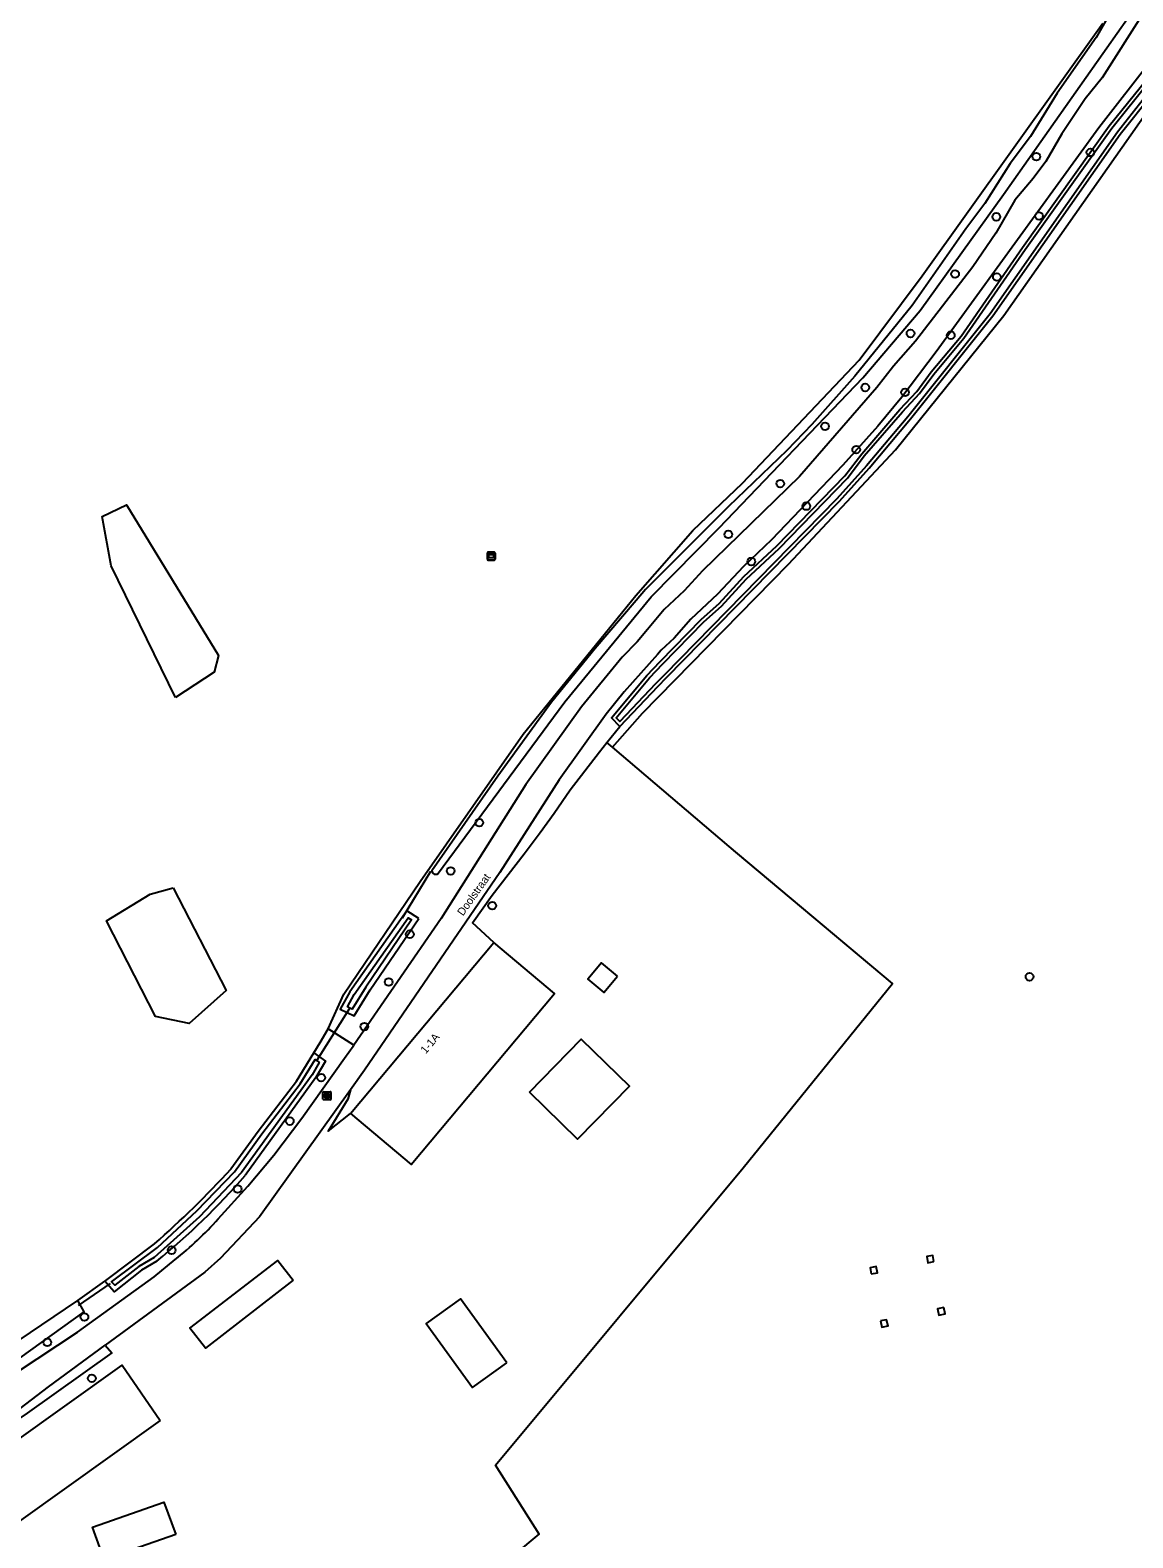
# Model space of a CAD drawing. Extents: x 164494 to 166241, y 382475 to 384494.
# Drawn here: x 165159.3 to 165298.8, y 383046.7 to 383237.3 of the extents above; entities that cross this region are included whole.
import ezdxf

# ---------------------------------------------------------------- set-up
doc = ezdxf.new("R2010")
doc.units = 0
for name, color, linetype in [('IMGEO_Boom', 7, 'Continuous'), ('IMGEO_Bouwland', 7, 'Continuous'), ('IMGEO_Duiker', 7, 'Continuous'), ('IMGEO_Grasland_overig', 7, 'Continuous'), ('IMGEO_Groenvoorziening', 7, 'Continuous'), ('IMGEO_Hek', 7, 'Continuous'), ('IMGEO_Hoogspanningsmast', 7, 'Continuous'), ('IMGEO_Loofbos', 7, 'Continuous'), ('IMGEO_Openbare_ruimte_label', 7, 'Continuous'), ('IMGEO_Pand', 7, 'Continuous'), ('IMGEO_Pand_nummerreeks', 7, 'Continuous'), ('IMGEO_Rijbaan_lokaal_halfverhard', 7, 'Continuous'), ('IMGEO_Rioolput', 7, 'Continuous'), ('IMGEO_Verklikker', 7, 'Continuous'), ('IMGEO_Waterloop', 7, 'Continuous')]:
    doc.layers.add(name, color=color, linetype=linetype)

msp = doc.modelspace()

# ---------------------------------------------------------------- linework, layer by layer
at = {"layer": 'IMGEO_Boom'}
for centre in [(165286.55, 383221.31), (165293.39, 383221.84), (165281.49, 383213.7), (165286.9, 383213.81), (165276.28, 383206.47), (165281.56, 383206.08), (165270.64, 383198.95), (165275.73, 383198.73), (165264.91, 383192.12), (165269.95, 383191.5), (165259.83, 383187.21), (165263.77, 383184.27), (165254.16, 383179.97), (165257.46, 383177.12), (165247.59, 383173.54), (165250.5, 383170.11), (165216.09, 383137.1), (165212.48, 383130.99), (165217.73, 383126.59), (165207.31, 383122.99), (165285.69, 383117.6), (165204.64, 383116.94), (165201.56, 383111.31), (165196.1, 383104.86), (165192.13, 383099.35), (165185.53, 383090.77), (165177.19, 383083.04), (165166.16, 383074.59), (165161.46, 383071.37), (165167.09, 383066.84)]:
    msp.add_circle(centre, 0.489, dxfattribs=at)
at = {"layer": 'IMGEO_Bouwland'}
for points in [[(165232.93, 383146.62), (165236.73, 383150.93), (165255.21, 383169.77), (165268.73, 383184.22), (165282.44, 383201.21), (165301.48, 383228.34), (165303.71, 383229.45), (165304.49, 383229.08), (165313.7, 383213.1), (165323.27, 383195.77), (165328.23, 383185.67), (165331.48, 383177.72), (165334.48, 383168.92), (165336.93, 383159.97), (165340.39, 383146.11), (165341.99, 383138.03)], [(165185, 383018.32), (165194.85, 383024.31), (165208.27, 383034.25), (165223.66, 383047.14), (165218.15, 383055.85), (165249.48, 383093.43), (165268.36, 383116.74), (165247.72, 383134.08), (165232.93, 383146.62)], [(165184.69, 383093.31), (165188.14, 383098.1), (165192.97, 383104.4), (165195.15, 383107.98)], [(165168.73, 383079.13), (165168.86, 383079.22), (165175, 383083.84)]]:
    msp.add_lwpolyline(points, dxfattribs=at)
msp.add_arc((165091.58, 383178.94), 126.51, 311.2584, 317.3955, dxfattribs=at)
at = {"layer": 'IMGEO_Duiker'}
for points in [[(165209.93, 383130.92), (165206.34, 383125)], [(165195.55, 383107.03), (165199.72, 383113.65)], [(165165.42, 383076.05), (165169.45, 383078.84)]]:
    msp.add_lwpolyline(points, dxfattribs=at)
at = {"layer": 'IMGEO_Grasland_overig'}
for points in [[(165197, 383111.02), (165198.96, 383115.4), (165208.62, 383129.64), (165221.63, 383148.27), (165235.88, 383165.81), (165243.09, 383174.04), (165249.4, 383180.04), (165264.13, 383195.59), (165272.13, 383206.26), (165294.98, 383238.21)], [(165233.88, 383149.26), (165232.83, 383150.35), (165237.3, 383155.71), (165238.99, 383157.46), (165244.19, 383162.81), (165246.45, 383164.79), (165249.54, 383168.2), (165253.72, 383172.09), (165262.35, 383180.93), (165264.46, 383183.73), (165269.29, 383189.33), (165271.45, 383191.63), (165273.23, 383194.09), (165277.04, 383198.62), (165284.8, 383209.82), (165295.77, 383225.19), (165300.55, 383231.16), (165301.32, 383231.86)], [(165232.24, 383147.21), (165233.88, 383149.26)], [(165217.94, 383121.93), (165215.23, 383124.42), (165217.74, 383127.91), (165221.76, 383133.17), (165223.8, 383135.85), (165225.58, 383138.3), (165227.61, 383141.23), (165231.32, 383146.06), (165232.24, 383147.21)], [(165208.43, 383124.96), (165206.95, 383125.96), (165199.74, 383115.69), (165198.52, 383113.49), (165200.29, 383112.66), (165202.29, 383115.96), (165208.43, 383124.96)], [(165195.15, 383107.98), (165195.96, 383109.31), (165197, 383111.02)], [(165200.23, 383108.95), (165197, 383111.02)], [(165195.15, 383107.98), (165196.66, 383106.95), (165195.43, 383104.86), (165186.49, 383092.48)], [(165199.81, 383103.29), (165199.49, 383102.14), (165196.97, 383098.1), (165199.79, 383100.32)], [(165175.31, 383081.64), (165173.36, 383080.5), (165169.91, 383077.78), (165168.73, 383079.13)], [(165165.33, 383076.66), (165168.73, 383079.13)]]:
    msp.add_lwpolyline(points, dxfattribs=at)
msp.add_arc((165116.7, 383153.32), 92.59, 309.2748, 318.9253, dxfattribs=at)
at = {"layer": 'IMGEO_Groenvoorziening'}
for points in [[(165233.88, 383149.26), (165238.71, 383154.35), (165239.79, 383155.44), (165261.65, 383177.73), (165265.39, 383181.92), (165270.62, 383188.15), (165281.06, 383201.19), (165297.16, 383224.15), (165301.31, 383229.4)], [(165232.93, 383146.62), (165232.24, 383147.21)], [(165168.79, 383071.02), (165169.63, 383070.04), (165158.92, 383062.43), (165147.97, 383055.13)]]:
    msp.add_lwpolyline(points, dxfattribs=at)
at = {"layer": 'IMGEO_Hek'}
for points in [[(165232.93, 383146.62), (165232.24, 383147.21)], [(165248.56, 383133.37), (165247.72, 383134.08), (165232.93, 383146.62)], [(165249.48, 383093.43), (165268.36, 383116.74), (165248.56, 383133.37)]]:
    msp.add_lwpolyline(points, dxfattribs=at)
at = {"layer": 'IMGEO_Hoogspanningsmast'}
for points in [[(165273.6, 383081.59), (165273.45, 383082.38), (165272.68, 383082.22), (165272.83, 383081.42), (165273.6, 383081.59)], [(165265.68, 383080.04), (165266.46, 383080.19), (165266.31, 383080.98), (165265.52, 383080.82), (165265.68, 383080.04)], [(165274.84, 383075.77), (165274.06, 383075.6), (165274.22, 383074.82), (165275.01, 383074.98), (165274.84, 383075.77)], [(165266.83, 383074.08), (165266.99, 383073.31), (165267.79, 383073.47), (165267.62, 383074.24), (165266.83, 383074.08)]]:
    msp.add_lwpolyline(points, dxfattribs=at)
at = {"layer": 'IMGEO_Loofbos'}
for points in [[(165177.67, 383152.9), (165169.55, 383169.59), (165168.39, 383175.79), (165171.46, 383177.28), (165183.1, 383158.25), (165182.55, 383156.14), (165177.67, 383152.9)], [(165177.36, 383128.85), (165184.08, 383115.87), (165179.39, 383111.69), (165175.14, 383112.58), (165168.94, 383124.68), (165174.45, 383128.05), (165177.36, 383128.85)]]:
    msp.add_lwpolyline(points, dxfattribs=at)
at = {"layer": 'IMGEO_Pand'}
for points in [[(165199.79, 383100.32), (165217.94, 383121.93)], [(165199.79, 383100.32), (165207.5, 383093.85), (165225.63, 383115.48), (165217.94, 383121.93)], [(165233.58, 383117.67), (165231.57, 383119.36), (165229.84, 383117.3), (165231.86, 383115.61), (165233.58, 383117.67)], [(165222.44, 383103.02), (165229, 383109.72), (165235.09, 383103.76), (165228.53, 383097.06), (165222.44, 383103.02)], [(165192.55, 383079.23), (165181.45, 383070.63), (165179.49, 383073.16), (165190.61, 383081.75), (165192.55, 383079.23)], [(165219.57, 383068.78), (165213.7, 383076.89), (165209.36, 383073.75), (165215.23, 383065.65), (165219.57, 383068.78)], [(165175.75, 383061.48), (165157.81, 383048.67), (165156.81, 383050.14), (165153.69, 383047.91), (165150.01, 383053.56), (165170.91, 383068.49), (165175.75, 383061.48)], [(165177.7, 383047.09), (165168.67, 383043.94), (165167.16, 383048.01), (165176.19, 383051.16), (165177.7, 383047.09)]]:
    msp.add_lwpolyline(points, dxfattribs=at)
at = {"layer": 'IMGEO_Rijbaan_lokaal_halfverhard'}
for points in [[(165300.11, 383239.48), (165294.86, 383231.27), (165292.71, 383228.62), (165289.79, 383224.2), (165287.74, 383220.71), (165286.16, 383218.55), (165283.85, 383215.8), (165281.41, 383211.62), (165278.5, 383207.39), (165271.28, 383197.97), (165268.48, 383194.82), (165266.39, 383192.1), (165256.58, 383180.86), (165244.32, 383168.93), (165241.99, 383166.4), (165239.47, 383164.03), (165237.38, 383161.51), (165236.08, 383159.95), (165234.16, 383158.04), (165229.01, 383151.75), (165221.98, 383141.91), (165211.27, 383124.97), (165200.23, 383108.95)], [(165301.1, 383233.5), (165294.45, 383224.95), (165273.9, 383196.62), (165269.53, 383190.91), (165266.52, 383187.24), (165262.08, 383182.29), (165253.04, 383172.85), (165249.5, 383169.5), (165246.23, 383165.97), (165242.87, 383162.82), (165240.74, 383160.44), (165239.08, 383158.89), (165238.62, 383158.37), (165234.41, 383153.64), (165232.13, 383150.82), (165226.21, 383142.5), (165218.7, 383130.81), (165201.6, 383105.79), (165199.81, 383103.29)], [(165183.08, 383087), (165186.84, 383091.11), (165190.1, 383095.04), (165193.65, 383099.72), (165199.07, 383107.32), (165200.16, 383108.84), (165200.23, 383108.95)], [(165199.81, 383103.29), (165188.28, 383087.23), (165183.37, 383082.04), (165181.4, 383080.25), (165168.79, 383071.02)], [(165145.27, 383058.94), (165150.95, 383062.46), (165153.38, 383064.63), (165157.7, 383067.66), (165165.26, 383072.66), (165174.96, 383079.68), (165177.63, 383081.87)], [(165147.97, 383055.13), (165152.79, 383059.07), (165161.61, 383065.76), (165168.79, 383071.02)]]:
    msp.add_lwpolyline(points, dxfattribs=at)
msp.add_arc((165151.38, 383115.19), 42.42, 308.2249, 318.3405, dxfattribs=at)
at = {"layer": 'IMGEO_Rioolput'}
for p, q in [((165196.33, 383102.14), (165196.33, 383102.99)), ((165196.4, 383103.06), (165197.25, 383103.06)), ((165196.81, 383102.84), (165196.84, 383102.84)), ((165196.84, 383102.28), (165196.81, 383102.28)), ((165197.33, 383102.99), (165197.33, 383102.14)), ((165197.25, 383102.06), (165196.4, 383102.06))]:
    msp.add_line(p, q, dxfattribs=at)
for points in [[(165196.33, 383102.14), (165196.33, 383102.99)], [(165196.4, 383103.06), (165197.25, 383103.06)], [(165196.92, 383102.76), (165196.66, 383102.76), (165196.66, 383102.36)], [(165196.66, 383102.36), (165196.79, 383102.36), (165196.79, 383102.52), (165196.8, 383102.52)], [(165196.84, 383102.68), (165196.79, 383102.68), (165196.79, 383102.6)], [(165196.79, 383102.6), (165196.84, 383102.6)], [(165196.84, 383102.49), (165196.92, 383102.36), (165197.06, 383102.36), (165196.99, 383102.49)], [(165197.33, 383102.99), (165197.33, 383102.14)], [(165197.25, 383102.06), (165196.4, 383102.06)]]:
    msp.add_lwpolyline(points, dxfattribs=at)
for centre, radius, start, end in [((165196.4, 383102.99), 0.0765, 91.552, 178.448), ((165196.4, 383102.99), 0.0765, 91.552, 178.448), ((165196.8, 383102.47), 0.0533, 26.0293, 88.6989), ((165196.85, 383102.58), 0.0964, 77.0061, 93.1865), ((165196.82, 383102.79), 0.19, 274.7715, 282.9687), ((165196.86, 383102.64), 0.0378, 276.6634, 79.6772), ((165196.91, 383102.65), 0.109, 350.3612, 89.416), ((165196.91, 383102.65), 0.112, 277.5842, 350.9817), ((165196.9, 383102.43), 0.108, 29.5134, 73.7905), ((165197.25, 383102.99), 0.0765, 1.552, 88.448), ((165197.25, 383102.99), 0.0765, 1.552, 88.448), ((165196.4, 383102.14), 0.0765, 181.552, 268.448), ((165196.4, 383102.14), 0.0765, 181.552, 268.448), ((165197.25, 383102.14), 0.0765, 271.552, 358.448), ((165197.25, 383102.14), 0.0765, 271.552, 358.448)]:
    msp.add_arc(centre, radius, start, end, dxfattribs=at)
for centre, major_axis, ratio, start_param, end_param in [((165196.81, 383102.56), (-0.387, 0.002), 0.722429, 4.712389, 7.853982), ((165196.84, 383102.56), (-0.39, 0.002), 0.717154, 1.570796, 4.712389)]:
    msp.add_ellipse(centre, major_axis=major_axis, ratio=ratio, start_param=start_param, end_param=end_param, dxfattribs=at)
at = {"layer": 'IMGEO_Verklikker'}
for p, q in [((165217.12, 383170.4), (165217.12, 383171.19)), ((165217.12, 383171.19), (165217.12, 383170.4)), ((165217.22, 383171.29), (165218.01, 383171.29)), ((165218.01, 383171.29), (165217.22, 383171.29)), ((165218.11, 383171.19), (165218.11, 383170.4)), ((165218.11, 383170.4), (165218.11, 383171.19)), ((165218.01, 383170.3), (165217.22, 383170.3)), ((165217.22, 383170.3), (165218.01, 383170.3))]:
    msp.add_line(p, q, dxfattribs=at)
for points in [[(165217.22, 383171.03), (165218.01, 383171.03), (165218.01, 383170.56), (165217.22, 383170.56), (165217.22, 383171.03)], [(165217.28, 383170.96), (165217.28, 383170.63), (165217.94, 383170.63), (165217.94, 383170.96), (165217.28, 383170.96)]]:
    msp.add_lwpolyline(points, dxfattribs=at)
for centre, start, end in [((165217.22, 383171.19), 90, 180), ((165217.22, 383171.19), 90, 180), ((165218.01, 383171.19), 0, 90), ((165218.01, 383171.19), 360, 90), ((165217.22, 383170.4), 180, 270), ((165217.22, 383170.4), 180, 270), ((165218.01, 383170.4), 270, 0), ((165218.01, 383170.4), 270, 0)]:
    msp.add_arc(centre, 0.1, start, end, dxfattribs=at)
at = {"layer": 'IMGEO_Waterloop'}
for points in [[(165296.93, 383241.33), (165294.12, 383236.39), (165289.2, 383229.34), (165285.8, 383223.84), (165283.26, 383220.44), (165280.02, 383215.37), (165277.63, 383212.19), (165270.83, 383202.49), (165263.6, 383193.55), (165258.15, 383187.46), (165255.01, 383184.17), (165247.6, 383177.07), (165237.1, 383166.57), (165235.92, 383165.18), (165230.75, 383159.11), (165225.22, 383152.32), (165218.46, 383142.98), (165210.09, 383131.01), (165210.13, 383130.88), (165210.18, 383130.75), (165210.24, 383130.69), (165210.4, 383130.6), (165210.5, 383130.59), (165210.68, 383130.59), (165210.82, 383130.6), (165226.93, 383152.39), (165237.82, 383165.67), (165246.45, 383174.39), (165264.61, 383193.36), (165271.84, 383201.86), (165282.4, 383216.51), (165298.1, 383238.79)], [(165301, 383229.7), (165296.82, 383224.4), (165280.72, 383201.44), (165270.29, 383188.42), (165265.07, 383182.21), (165261.33, 383178.03), (165239.48, 383155.74), (165238.4, 383154.65), (165233.88, 383149.88), (165233.41, 383150.37), (165237.61, 383155.42), (165239.3, 383157.16), (165244.48, 383162.5), (165246.75, 383164.48), (165249.84, 383167.9), (165254.02, 383171.78), (165262.68, 383180.65), (165264.79, 383183.46), (165269.61, 383189.05), (165271.78, 383191.35), (165273.57, 383193.82), (165277.38, 383198.35), (165285.15, 383209.57), (165296.11, 383224.93), (165300.87, 383230.86)], [(165200.29, 383115.35), (165207.11, 383125.07), (165207.52, 383124.79), (165201.75, 383116.31), (165200.04, 383113.5), (165199.72, 383113.65), (165199.42, 383113.79), (165200.29, 383115.35)], [(165194.94, 383105.21), (165186.02, 383092.85), (165180.72, 383087.25), (165174.96, 383082.12), (165173.02, 383080.99), (165169.99, 383078.6), (165169.6, 383079.04), (165175.38, 383083.38), (165180.39, 383088.02), (165185.15, 383092.92), (165188.61, 383097.75), (165193.46, 383104.06), (165195.33, 383107.13), (165195.55, 383107.03), (165195.86, 383106.77), (165194.94, 383105.21)], [(165151.82, 383066.74), (165153, 383067.83), (165157.78, 383071.58), (165165.33, 383076.66)], [(165151.82, 383066.74), (165152.43, 383065.87), (165154.94, 383067.08), (165158.05, 383069.44), (165166.13, 383075.22), (165165.33, 383076.66)]]:
    msp.add_lwpolyline(points, dxfattribs=at)

# ---------------------------------------------------------------- texts
at = {"layer": 'IMGEO_Openbare_ruimte_label'}
msp.add_text('Doolstraat', height=1, rotation=54.6089, dxfattribs=at).set_placement((165214.04, 383125.23))
at = {"layer": 'IMGEO_Pand_nummerreeks'}
msp.add_text('1-1A', height=1, rotation=49.9676, dxfattribs=at).set_placement((165209.33, 383107.79))

doc.saveas('drawing.dxf')
